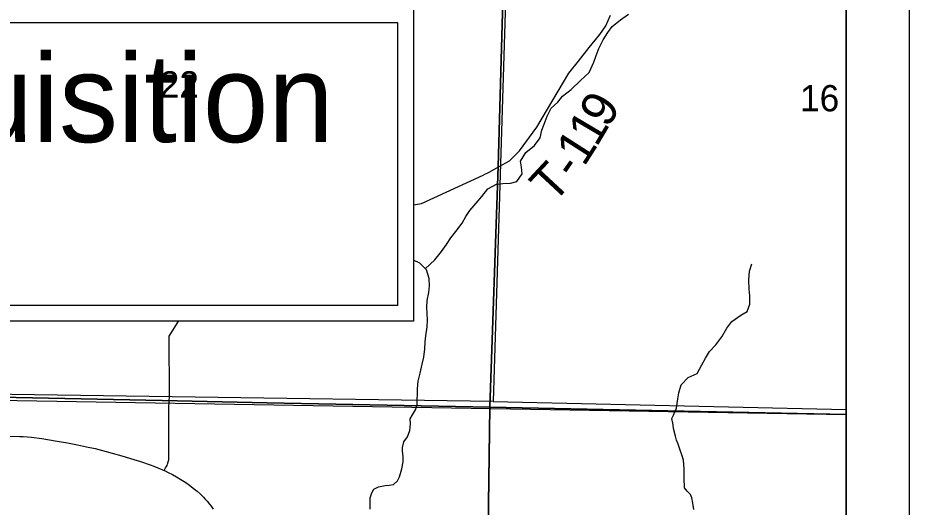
# Model space of a CAD drawing. Extents: x -1.2 to 34, y -8.5 to 22.
# Drawn here: x 7.582 to 9, y 17.528 to 18.307 of the extents above; entities that cross this region are included whole.
import ezdxf

# ---------------------------------------------------------------- set-up
doc = ezdxf.new("R2010")
doc.units = 0
for name, color, linetype in [('DV_X_County_Line', 7, 'Continuous'), ('GM_X_Minor_River', 7, 'Continuous'), ('GM_X_Section', 7, 'Continuous'), ('GM_X_Section_Text', 7, 'Continuous'), ('GM_X_State_Route', 7, 'Continuous'), ('GM_X_Township_Road', 7, 'Continuous'), ('GM_X_Township_Road_Text', 7, 'Continuous'), ('GM_X_Unincorporated_Text', 7, 'Continuous'), ('SH_Cut_Line', 7, 'Continuous'), ('SH_Data', 7, 'Continuous'), ('SH_Text', 7, 'Continuous')]:
    doc.layers.add(name, color=color, linetype=linetype)

msp = doc.modelspace()

# ---------------------------------------------------------------- linework, layer by layer
at = {"layer": 'DV_X_County_Line'}
msp.add_line((6.6617, 17.7133), (8.9, 17.6758), dxfattribs=at)
at = {"layer": 'GM_X_Minor_River'}
for points in [[(8.2301, 17.9076), (8.2454, 17.922), (8.2559, 17.935), (8.2638, 17.9461), (8.2705, 17.9571), (8.2784, 17.9671), (8.2886, 17.9805), (8.2946, 17.9908), (8.3009, 18.0003), (8.3111, 18.0122), (8.3201, 18.0229), (8.3295, 18.0351), (8.3431, 18.0424), (8.3534, 18.0433), (8.3655, 18.0441), (8.3758, 18.0469), (8.3844, 18.0591), (8.3832, 18.0694), (8.3816, 18.0792), (8.3898, 18.093), (8.4038, 18.1041), (8.4128, 18.1163), (8.4157, 18.1285), (8.4191, 18.138), (8.4239, 18.1506), (8.4303, 18.1632), (8.4408, 18.1731), (8.4483, 18.1827), (8.4619, 18.1934), (8.477, 18.2076), (8.4909, 18.2203), (8.4984, 18.2367), (8.5021, 18.2473), (8.5062, 18.2584), (8.5133, 18.2725), (8.5204, 18.2839), (8.5272, 18.2935), (8.5408, 18.3042), (8.5536, 18.3131)], [(8.2172, 17.6909), (8.2175, 17.7163), (8.2185, 17.7285), (8.2218, 17.7414), (8.2251, 17.7559), (8.2277, 17.7669), (8.2291, 17.7799), (8.2298, 17.7912), (8.2308, 17.8007), (8.233, 17.8152), (8.2337, 17.8258), (8.2332, 17.8365), (8.2323, 17.8459), (8.233, 17.8573), (8.2356, 17.8699), (8.2366, 17.8805), (8.2361, 17.8923), (8.2318, 17.9059), (8.2211, 17.9165), (8.2113, 17.9211)], [(8.6298, 17.6857), (8.632, 17.7005), (8.6334, 17.71), (8.6371, 17.723), (8.6484, 17.7344), (8.6624, 17.741), (8.6703, 17.7548), (8.6759, 17.7654), (8.6823, 17.7757), (8.6924, 17.7865), (8.7018, 17.7994), (8.71, 17.8132), (8.7179, 17.8235), (8.7319, 17.8339), (8.7421, 17.8397), (8.7462, 17.8515), (8.7465, 17.8644), (8.7452, 17.8754), (8.7451, 17.8898), (8.7461, 17.9039), (8.7495, 17.9157)], [(8.1423, 17.525), (8.1422, 17.5357), (8.1424, 17.5426), (8.145, 17.551), (8.1483, 17.5564), (8.1554, 17.5603), (8.1607, 17.5615), (8.1664, 17.5623), (8.1728, 17.5628), (8.1792, 17.5641), (8.1856, 17.5699), (8.1889, 17.5764), (8.1925, 17.589), (8.1946, 17.6001), (8.1949, 17.6081), (8.194, 17.6176), (8.1939, 17.6229), (8.1961, 17.6321), (8.2016, 17.6402), (8.2053, 17.6502), (8.2067, 17.6605), (8.2062, 17.6688), (8.2097, 17.6748), (8.2145, 17.6829), (8.2172, 17.6909)], [(8.6299, 17.6345), (8.628, 17.6409), (8.6251, 17.6531), (8.6243, 17.6592), (8.6223, 17.669), (8.6251, 17.6746), (8.6269, 17.6799), (8.6298, 17.6857)], [(8.6576, 17.5244), (8.6556, 17.5343), (8.6543, 17.5427), (8.652, 17.5483), (8.6466, 17.5536), (8.6427, 17.5589), (8.6418, 17.5741), (8.6419, 17.589), (8.641, 17.6027), (8.639, 17.6099), (8.6362, 17.6174), (8.6323, 17.6281), (8.6299, 17.6345)]]:
    msp.add_lwpolyline(points, dxfattribs=at)
at = {"layer": 'GM_X_Section'}
msp.add_lwpolyline([(7.3297, 18.3243), (7.3389, 18.7336), (8.3694, 18.7126), (8.3383, 17.696), (7.3158, 17.711), (7.3184, 17.8243)], dxfattribs=at)
msp.add_lwpolyline([(8.9, 17.6837), (8.9, 18.7005), (8.3694, 18.7126), (8.3383, 17.696)], close=True, dxfattribs=at)
at = {"layer": 'GM_X_State_Route'}
msp.add_lwpolyline([(7.5666, 17.6411), (7.5849, 17.6407), (7.5903, 17.6405), (7.5971, 17.64), (7.6035, 17.6394), (7.62, 17.6371), (7.6287, 17.6358), (7.6444, 17.6332), (7.6605, 17.6302), (7.6766, 17.6273), (7.6911, 17.6243), (7.7046, 17.6213), (7.7224, 17.6168), (7.732, 17.6142), (7.747, 17.6099), (7.7665, 17.604), (7.777, 17.6006), (7.792, 17.5954), (7.7983, 17.5931), (7.8106, 17.5882), (7.8144, 17.5865), (7.8162, 17.5857), (7.821, 17.5833), (7.8276, 17.5798), (7.834, 17.5762), (7.8409, 17.572), (7.8488, 17.567), (7.8548, 17.5628), (7.8608, 17.5583), (7.867, 17.5533), (7.8718, 17.5491), (7.8772, 17.5439), (7.8795, 17.5414), (7.8829, 17.5376), (7.8868, 17.5329), (7.8894, 17.5293), (7.8924, 17.5246)], dxfattribs=at)
at = {"layer": 'GM_X_Township_Road'}
for points in [[(8.3328, 18.0622), (8.3463, 18.0698), (8.3641, 18.0798), (8.3798, 18.0953), (8.4074, 18.133), (8.4585, 18.219), (8.4738, 18.2385), (8.4909, 18.2603), (8.5079, 18.2808), (8.5175, 18.2946), (8.5249, 18.3115)], [(8.2113, 18.0094), (8.2239, 18.0116), (8.3223, 18.0569), (8.3259, 18.0586), (8.3286, 18.0598), (8.3328, 18.0622)], [(7.8232, 17.7048), (7.8224, 17.8001), (7.8369, 17.8234), (7.8378, 17.8243)], [(7.8144, 17.5865), (7.8169, 17.5905), (7.8192, 17.5944), (7.8201, 17.5966), (7.8211, 17.5999), (7.8217, 17.6033), (7.822, 17.6068), (7.8221, 17.612), (7.8219, 17.656), (7.8219, 17.672), (7.8221, 17.6864), (7.8226, 17.6965), (7.8232, 17.7048)]]:
    msp.add_lwpolyline(points, dxfattribs=at)
at = {"layer": 'GM_X_Unincorporated_Text'}
for p, q in [((7.8111, 17.6977), (7.3722, 17.707)), ((7.9782, 17.6941), (7.8111, 17.6977)), ((8.3326, 17.6871), (7.9782, 17.6941)), ((8.3265, 17.2224), (8.3326, 17.6871))]:
    msp.add_line(p, q, dxfattribs=at)
msp.add_lwpolyline([(6.665, 17.7216), (6.6751, 17.7216), (6.7322, 17.7204), (7.1254, 17.7122), (7.3722, 17.707), (7.8111, 17.6977), (7.9782, 17.6941), (8.3326, 17.6871), (8.3461, 18.0704), (8.364, 18.7117), (8.3686, 18.968), (8.382, 19.7108), (8.4089, 20.6815), (8.4143, 20.9), (2.465, 20.9)], dxfattribs=at)
for points in [[(8.9, 17.6758), (8.9, 20.9), (8.4143, 20.9), (8.4089, 20.6815), (8.382, 19.7108), (8.3686, 18.968), (8.364, 18.7117), (8.3461, 18.0704), (8.3326, 17.6871)], [(8.2551, 14.1), (8.9, 14.1), (8.9, 17.6758), (8.3326, 17.6871), (8.3265, 17.2224), (8.3029, 16.2873), (8.2955, 15.9378), (8.2794, 15.1757), (8.2772, 15.0742)]]:
    msp.add_lwpolyline(points, close=True, dxfattribs=at)
at = {"layer": 'SH_Cut_Line'}
for points in [[(6.665, 17.7216), (6.6751, 17.7216), (6.7322, 17.7204), (7.1254, 17.7122), (7.3722, 17.707), (7.8111, 17.6977), (7.9782, 17.6941), (8.3326, 17.6871), (8.9, 17.6758), (8.9, 20.9), (2.465, 20.9)], [(2.3586, 14.1), (8.9, 14.1), (8.9, 17.6758), (8.3326, 17.6871), (7.9782, 17.6941), (7.8111, 17.6977), (7.3722, 17.707), (7.1254, 17.7122), (6.7322, 17.7204), (6.6751, 17.7216), (6.665, 17.7216)]]:
    msp.add_lwpolyline(points, dxfattribs=at)
at = {"layer": 'SH_Data'}
for p, q in [((9, 21), (9, 14)), ((9, 21), (9, 14)), ((8.9, 20.9), (8.9, 14.1)), ((8.9, 20.9), (8.9, 14.1))]:
    msp.add_line(p, q, dxfattribs=at)
at = {"layer": 'SH_Text'}
for p, q in [((8.1863, 18.2993), (6.5982, 18.2993)), ((8.1863, 17.8493), (8.1863, 18.2993)), ((8.1863, 17.8493), (6.5982, 17.8493))]:
    msp.add_line(p, q, dxfattribs=at)
msp.add_lwpolyline([(6.5732, 17.8243), (6.5732, 18.3243), (8.2113, 18.3243), (8.2113, 17.8243), (6.7063, 17.8243)], dxfattribs=at)

# ---------------------------------------------------------------- texts
at = {"layer": 'GM_X_Section_Text'}
for s, p in [('22', (7.8076, 18.1804)), ('16', (8.8264, 18.1584))]:
    msp.add_text(s, height=0.04186, rotation=0, dxfattribs=at).set_placement(p)
at = {"layer": 'GM_X_Township_Road_Text'}
for s, rotation, p in [('9', 58.7962, (8.5204, 18.1302)), ('1', 59.3217, (8.5026, 18.1002)), ('1', 57.3696, (8.4826, 18.0689)), ('T', 47.0944, (8.4335, 18.0099)), ('-', 55.1579, (8.4679, 18.0478))]:
    msp.add_text(s, height=0.0568, rotation=rotation, dxfattribs=at).set_placement(p)
at = {"layer": 'SH_Text'}
msp.add_text('Begin Acquisition', height=0.14, dxfattribs=at).set_placement((6.6482, 18.1094))

doc.saveas('drawing.dxf')
